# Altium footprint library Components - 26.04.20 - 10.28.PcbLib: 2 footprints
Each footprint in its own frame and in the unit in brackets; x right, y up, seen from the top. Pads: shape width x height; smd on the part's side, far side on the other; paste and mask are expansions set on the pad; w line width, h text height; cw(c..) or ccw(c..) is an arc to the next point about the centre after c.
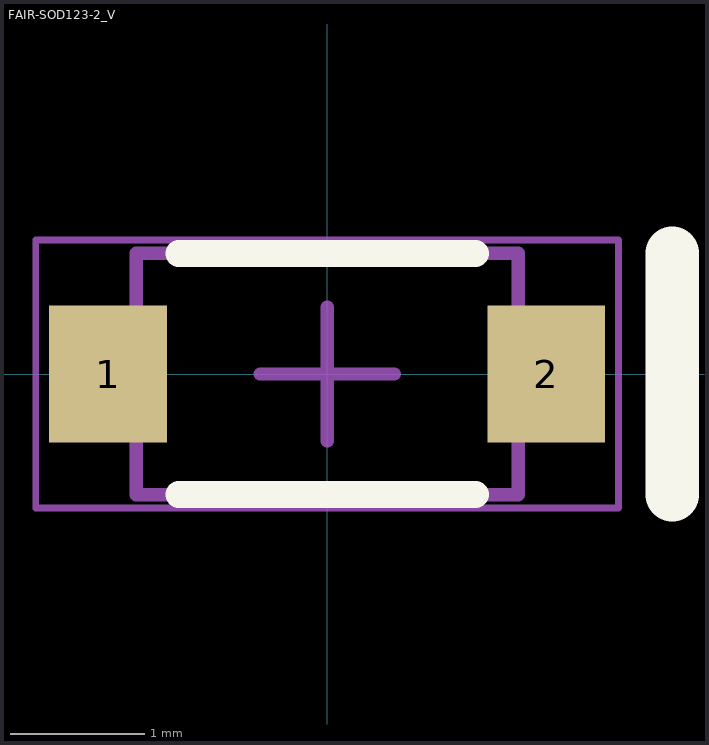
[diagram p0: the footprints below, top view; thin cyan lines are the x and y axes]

## FAIR-SOD123-2_V [mm] "SOD123, 2-Leads, Body 1.80x2.85mm"
height 1.28
pads (2):
  rect 0.88x1.02 smd: 1(-1.635,0) 2(1.635,0)
Top Overlay:
  lines w0.2: -1.108,-0.9 1.108,-0.9 ; -1.108,0.9 1.108,0.9
  lines w0.4: 2.575,-0.9 2.575,0.9
Mechanical 13:
  lines w0.1: -1.425,-0.9 1.425,-0.9 1.425,0.9 -1.425,0.9 -1.425,-0.9
Mechanical 15:
  lines w0.05: -2.175,-1 2.175,-1 2.175,1 -2.175,1 -2.175,-1
  lines w0.1: -0.5,0 0.5,0 ; 0,-0.5 0,0.5
3D body: height 1.28, standoff 0, extent -1.425,-0.9 1.425,0.9

## PCBComponent_1 [mm]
